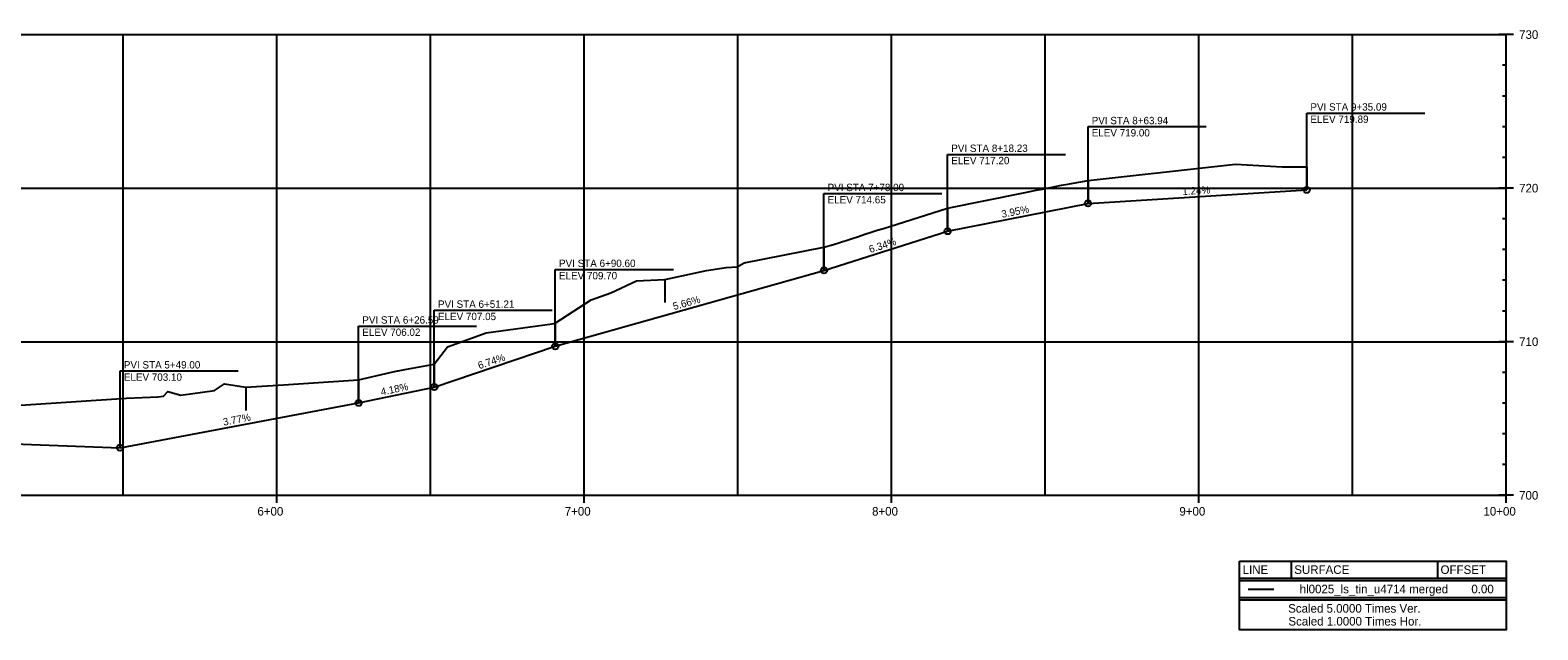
# Model space of a CAD drawing. Extents: x 1487507 to 1489130, y 497211 to 499439.
# Drawn here: x 1488039 to 1488529.6, y 497211.2 to 497406.4 of the extents above; entities that cross this region are included whole.
import ezdxf

# ---------------------------------------------------------------- set-up
doc = ezdxf.new("R2010")
doc.units = 0
doc.layers.add('Default', color=7, linetype='Continuous')

msp = doc.modelspace()

# ---------------------------------------------------------------- linework, layer by layer
at = {"layer": 'Default'}
for p, q in [((1487519.3, 497404.95), (1488519.3, 497404.95)), ((1487519.3, 497404.95), (1488519.3, 497404.95)), ((1488069.3, 497254.95), (1488069.3, 497404.95)), ((1488119.3, 497254.95), (1488119.3, 497404.95)), ((1488169.3, 497254.95), (1488169.3, 497404.95)), ((1488219.3, 497254.95), (1488219.3, 497404.95)), ((1488269.3, 497254.95), (1488269.3, 497404.95)), ((1488319.3, 497254.95), (1488319.3, 497404.95)), ((1488369.3, 497254.95), (1488369.3, 497404.95)), ((1488419.3, 497254.95), (1488419.3, 497404.95)), ((1488469.3, 497254.95), (1488469.3, 497404.95)), ((1488521.7, 497404.95), (1488516.9, 497404.95)), ((1488521.7, 497404.95), (1488516.9, 497404.95)), ((1488519.3, 497254.95), (1488519.3, 497404.95)), ((1488519.3, 497394.95), (1488518.1, 497394.95)), ((1488519.3, 497384.95), (1488518.1, 497384.95)), ((1488454.39, 497354.39), (1488454.39, 497379.39)), ((1488454.39, 497379.39), (1488492.79, 497379.39)), ((1488383.23, 497349.97), (1488383.23, 497374.97)), ((1488383.23, 497374.97), (1488421.63, 497374.97)), ((1488519.3, 497374.95), (1488518.1, 497374.95)), ((1488337.53, 497340.94), (1488337.53, 497365.94)), ((1488337.53, 497365.94), (1488375.93, 497365.94)), ((1488519.3, 497364.95), (1488518.1, 497364.95)), ((1488383.23, 497357.47), (1488383.23, 497349.97)), ((1488454.39, 497361.89), (1488454.39, 497354.39)), ((1487519.3, 497354.95), (1488519.3, 497354.95)), ((1488297.3, 497328.19), (1488297.3, 497353.19)), ((1488297.3, 497353.19), (1488335.7, 497353.19)), ((1488383.23, 497349.97), (1488454.39, 497354.39)), ((1488521.7, 497354.95), (1488516.9, 497354.95)), ((1488337.53, 497340.94), (1488383.23, 497349.97)), ((1488337.53, 497348.44), (1488337.53, 497340.94)), ((1488519.3, 497344.95), (1488518.1, 497344.95)), ((1488297.3, 497328.19), (1488337.53, 497340.94)), ((1488297.3, 497335.69), (1488297.3, 497328.19)), ((1488519.3, 497334.95), (1488518.1, 497334.95)), ((1488209.9, 497303.47), (1488209.9, 497328.47)), ((1488209.9, 497328.47), (1488248.3, 497328.47)), ((1488209.9, 497303.47), (1488297.3, 497328.19)), ((1488245.53, 497325.19), (1488245.53, 497317.69)), ((1488519.3, 497324.95), (1488518.1, 497324.95)), ((1488170.51, 497290.19), (1488170.51, 497315.19)), ((1488170.51, 497315.19), (1488208.91, 497315.19)), ((1488519.3, 497314.95), (1488518.1, 497314.95)), ((1488145.89, 497285.05), (1488145.89, 497310.05)), ((1488145.89, 497310.05), (1488184.29, 497310.05)), ((1488209.9, 497310.97), (1488209.9, 497303.47)), ((1487519.3, 497304.95), (1488519.3, 497304.95)), ((1488170.51, 497290.19), (1488209.9, 497303.47)), ((1488521.7, 497304.95), (1488516.9, 497304.95)), ((1488068.3, 497270.44), (1488068.3, 497295.44)), ((1488068.3, 497295.44), (1488106.7, 497295.44)), ((1488170.51, 497297.69), (1488170.51, 497290.19)), ((1488519.3, 497294.95), (1488518.1, 497294.95)), ((1488109.16, 497290.11), (1488109.16, 497282.61)), ((1488145.89, 497292.55), (1488145.89, 497285.05)), ((1488145.89, 497285.05), (1488170.51, 497290.19)), ((1488068.3, 497270.44), (1488145.89, 497285.05)), ((1488519.3, 497284.95), (1488518.1, 497284.95)), ((1488519.3, 497274.95), (1488518.1, 497274.95)), ((1487982.07, 497273.67), (1488068.3, 497270.44)), ((1487982.07, 497273.67), (1488068.3, 497270.44)), ((1488519.3, 497264.95), (1488518.1, 497264.95)), ((1487519.3, 497254.95), (1488519.3, 497254.95)), ((1488069.3, 497254.95), (1488069.3, 497256.15)), ((1488119.3, 497252.55), (1488119.3, 497257.35)), ((1488169.3, 497254.95), (1488169.3, 497256.15)), ((1488219.3, 497252.55), (1488219.3, 497257.35)), ((1488269.3, 497254.95), (1488269.3, 497256.15)), ((1488319.3, 497252.55), (1488319.3, 497257.35)), ((1488369.3, 497254.95), (1488369.3, 497256.15)), ((1488419.3, 497252.55), (1488419.3, 497257.35)), ((1488469.3, 497254.95), (1488469.3, 497256.15)), ((1488521.7, 497254.95), (1488516.9, 497254.95)), ((1488519.3, 497252.55), (1488519.3, 497257.35)), ((1488449.3, 497233.55), (1488449.3, 497227.95)), ((1488496.9, 497233.55), (1488496.9, 497227.95)), ((1488432.5, 497227.95), (1488519.3, 497227.95)), ((1488432.5, 497227.25), (1488519.3, 497227.25)), ((1488432.5, 497221.65), (1488519.3, 497221.65)), ((1488432.5, 497220.95), (1488519.3, 497220.95)), ((1488435.3, 497224.45), (1488443.7, 497224.45))]:
    msp.add_line(p, q, dxfattribs=at)
for points in [[(1488035.99, 497284.34), (1488070.32, 497286.6), (1488080.55, 497287), (1488082.42, 497287.25), (1488083.79, 497288.79), (1488088, 497287.57), (1488099.02, 497289.06), (1488102.25, 497291.29), (1488109.16, 497290.11), (1488121.48, 497290.88), (1488145.89, 497292.55), (1488156.14, 497294.92), (1488158.53, 497295.47), (1488158.77, 497295.52), (1488160.93, 497295.94), (1488163.32, 497296.39), (1488165.71, 497296.82), (1488170.51, 497297.69), (1488174.77, 497303.27), (1488187.38, 497307.83), (1488208.84, 497310.81), (1488209.9, 497310.97), (1488221.52, 497318.58), (1488227.91, 497320.83), (1488236.27, 497324.75), (1488245.53, 497325.19), (1488259.1, 497328.09), (1488265.46, 497329.09), (1488269.09, 497329.34), (1488271.37, 497330.59), (1488297.3, 497335.69), (1488300.44, 497336.65), (1488302.47, 497337.27), (1488303.07, 497337.45), (1488304.5, 497337.93), (1488306.54, 497338.59), (1488308.57, 497339.26), (1488310.6, 497339.92), (1488312.64, 497340.57), (1488314.67, 497341.23), (1488316.71, 497341.87), (1488318.74, 497342.52), (1488337.53, 497348.44), (1488362.23, 497353.43), (1488364.3, 497353.85), (1488366.36, 497354.26), (1488368.43, 497354.67), (1488370.5, 497355.07), (1488372.57, 497355.48), (1488374.63, 497355.87), (1488376.7, 497356.27), (1488377.2, 497356.36), (1488383.23, 497357.47), (1488426.34, 497362.17), (1488431.22, 497362.76), (1488446.41, 497361.92), (1488454.39, 497361.89)], [(1488068.3, 497270.44), (1488145.89, 497285.05), (1488170.51, 497290.19), (1488209.9, 497303.47), (1488209.9, 497303.47), (1488297.3, 497328.19), (1488337.53, 497340.94), (1488383.23, 497349.97), (1488454.39, 497354.39)]]:
    msp.add_lwpolyline(points, dxfattribs=at)
msp.add_lwpolyline([(1488432.5, 497233.55), (1488519.3, 497233.55), (1488519.3, 497211.15), (1488432.5, 497211.15)], close=True, dxfattribs=at)
for centre in [(1488454.39, 497354.39), (1488383.23, 497349.97), (1488337.53, 497340.94), (1488297.3, 497328.19), (1488209.9, 497303.47), (1488170.51, 497290.19), (1488145.89, 497285.05), (1488068.3, 497270.44)]:
    msp.add_circle(centre, 1, dxfattribs=at)

# ---------------------------------------------------------------- texts
for s, height, p in [('730', 2.8, (1488523.5, 497403.55)), ('730', 2.8, (1488523.5, 497403.55)), ('PVI STA 9+35.09', 2.4, (1488455.59, 497380.19)), ('PVI STA 8+63.94', 2.4, (1488384.43, 497375.77)), ('ELEV 719.89', 2.4, (1488455.59, 497376.19)), ('ELEV 719.00', 2.4, (1488384.43, 497371.77)), ('PVI STA 8+18.23', 2.4, (1488338.73, 497366.74)), ('ELEV 717.20', 2.4, (1488338.73, 497362.74)), ('PVI STA 7+78.00', 2.4, (1488298.5, 497353.99)), ('ELEV 714.65', 2.4, (1488298.5, 497349.99)), ('720', 2.8, (1488523.5, 497353.55)), ('PVI STA 6+90.60', 2.4, (1488211.1, 497329.27)), ('ELEV 709.70', 2.4, (1488211.1, 497325.27)), ('PVI STA 6+51.21', 2.4, (1488171.71, 497315.99)), ('PVI STA 6+26.59', 2.4, (1488147.09, 497310.85)), ('ELEV 707.05', 2.4, (1488171.71, 497311.99)), ('ELEV 706.02', 2.4, (1488147.09, 497306.85)), ('710', 2.8, (1488523.5, 497303.55)), ('PVI STA 5+49.00', 2.4, (1488069.5, 497296.24)), ('ELEV 703.10', 2.4, (1488069.5, 497292.24)), ('700', 2.8, (1488523.5, 497253.55)), ('6+00', 2.8, (1488112.96, 497248.35)), ('7+00', 2.8, (1488212.96, 497248.35)), ('8+00', 2.8, (1488312.96, 497248.35)), ('9+00', 2.8, (1488412.96, 497248.35)), ('10+00', 2.8, (1488511.9, 497248.35)), (' LINE ', 2.8, (1488432.5, 497229.35)), (' SURFACE         ', 2.8, (1488449.3, 497229.35)), (' OFFSET ', 2.8, (1488496.9, 497229.35)), ('hl0025_ls_tin_u4714 merged', 2.8, (1488452.1, 497223.05)), ('0.00', 2.8, (1488507.96, 497223.05)), ('Scaled 5.0000 Times Ver.', 2.8, (1488448.36, 497216.75)), ('Scaled 1.0000 Times Hor.', 2.8, (1488448.43, 497212.55))]:
    msp.add_text(s, height=height, dxfattribs=at).set_placement(p)
for s, rotation, p in [('1.24%', 3.5522, (1488413.97, 497352.68)), ('3.95%', 11.179, (1488355.29, 497345.27)), ('6.34%', 17.5897, (1488312.38, 497333.81)), ('5.66%', 15.7895, (1488248.54, 497315.23)), ('6.74%', 18.6322, (1488185.18, 497295.98)), ('4.18%', 11.7949, (1488153.34, 497287.42)), ('3.77%', 10.664, (1488102, 497277.6))]:
    msp.add_text(s, height=2.4, rotation=rotation, dxfattribs=at).set_placement(p)

doc.saveas('drawing.dxf')
